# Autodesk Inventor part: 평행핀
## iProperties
IsCustomPart: 0
Created: 2009-02
Part Number: 평행핀
Material: 강, 연강
Description: 평행 핀
Document SubType Name: Modeling
Standard: KS B 1320
Designer: KYOUNG IL JANG
Standards Organization: KS
Language: ko-KR
Size Designation: B 5 x  20
Categories: <MemberInstance><Categories><Category DisplayName="조임쇠" InternalName="e4da775c-781d-43d5-af7c-5136215cf5a6" Mnemonic="FSTN"><Category DisplayName="핀" InternalNa
Density: 1 g/cm^3
Author: KYOUNG IL JANG
